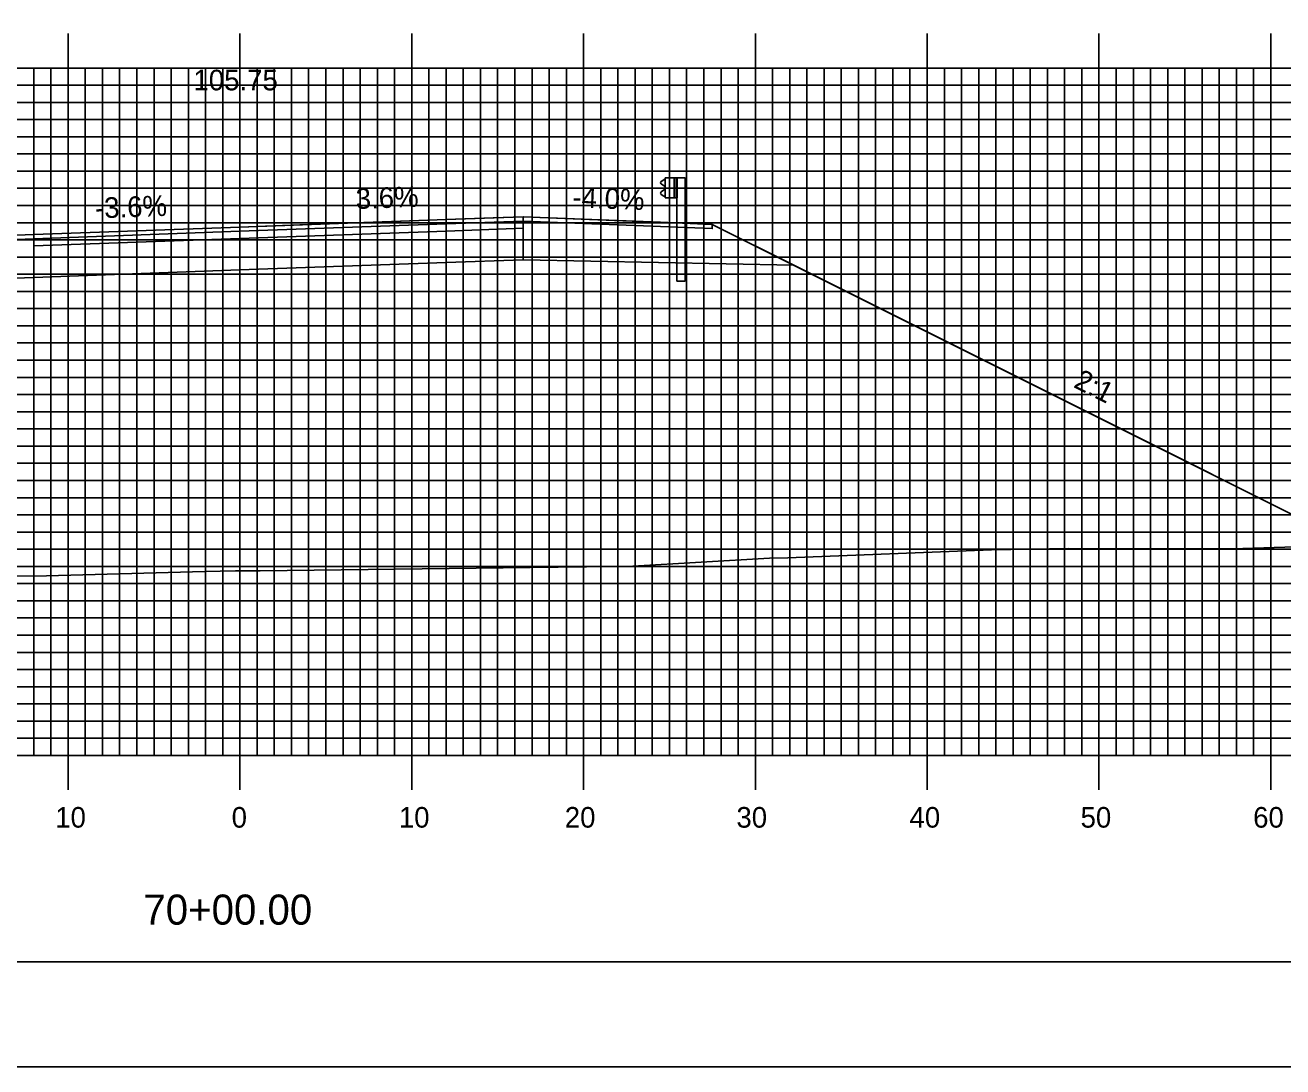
# Model space of a CAD drawing. Extents: x 1760217 to 1760560, y 442591 to 442811.
# Drawn here: x 1760370.2 to 1760443.4, y 442590.5 to 442651.2 of the extents above; entities that cross this region are included whole.
import ezdxf

# ---------------------------------------------------------------- set-up
doc = ezdxf.new("R2010")
doc.units = 0
for name, color, linetype in [('ANNOTATION', 7, 'Continuous'), ('BORDER', 7, 'Continuous'), ('D_Guardrail_Beam_Rt', 7, 'Continuous'), ('D_Roadway_Centerline', 7, 'Continuous'), ('D_Roadway_Centerline_Text', 7, 'Continuous'), ('D_Roadway_Edge_Shoulder', 7, 'Continuous'), ('D_Roadway_Edge_TW', 7, 'Continuous'), ('D_Roadway_Pavement', 7, 'Continuous'), ('D_Roadway_SlopeLines', 7, 'Continuous'), ('D_Roadway_SubGrade', 7, 'Continuous'), ('H_V ANNOTATION', 7, 'Continuous'), ('MAJOR', 7, 'Continuous'), ('MINOR', 7, 'Continuous'), ('PLOT BOUNDARY', 7, 'Continuous'), ('S_Roadway_Centerline', 7, 'Continuous')]:
    doc.layers.add(name, color=color, linetype=linetype)

msp = doc.modelspace()

# ---------------------------------------------------------------- linework, layer by layer
at = {"layer": 'BORDER'}
msp.add_lwpolyline([(1760233.101, 442596.665), (1760553.101, 442596.665), (1760553.101, 442806.665), (1760233.101, 442806.665)], close=True, dxfattribs=at)
at = {"layer": 'D_Guardrail_Beam_Rt'}
for p, q in [((1760407.369, 442642.167), (1760407.226, 442642.067)), ((1760407.459, 442642.188), (1760407.385, 442642.174)), ((1760407.459, 442642.272), (1760408.147, 442642.272)), ((1760407.459, 442641.105), (1760407.459, 442642.272)), ((1760407.98, 442642.272), (1760407.98, 442641.105)), ((1760408.084, 442642.272), (1760408.084, 442641.105)), ((1760408.147, 442642.272), (1760408.617, 442642.272)), ((1760408.147, 442642.272), (1760408.147, 442641.105)), ((1760408.617, 442642.272), (1760408.617, 442636.272)), ((1760407.226, 442641.924), (1760407.421, 442641.788)), ((1760407.421, 442641.589), (1760407.226, 442641.453)), ((1760407.226, 442641.309), (1760407.369, 442641.209)), ((1760407.455, 442641.723), (1760407.455, 442641.653)), ((1760407.385, 442641.203), (1760407.459, 442641.188)), ((1760408.147, 442641.105), (1760407.459, 442641.105)), ((1760408.126, 442636.272), (1760408.126, 442641.105)), ((1760408.126, 442636.272), (1760408.617, 442636.272))]:
    msp.add_line(p, q, dxfattribs=at)
for centre, major_axis, start_param, end_param in [((1760407.276, 442641.995), (-0.0877, 0), 5.323254, 7.243116), ((1760407.393, 442642.133), (-0.0417, 0), 4.907132, 5.323254), ((1760407.276, 442641.381), (-0.0877, 0), 5.323254, 7.243116), ((1760407.376, 442641.723), (0.0789, 0), 0, 0.959931), ((1760407.376, 442641.653), (0.0789, 0), 5.323254, 6.283185), ((1760407.393, 442641.243), (-0.0417, 0), 0.959931, 1.376053)]:
    msp.add_ellipse(centre, major_axis=major_axis, ratio=0.995501, start_param=start_param, end_param=end_param, dxfattribs=at)
at = {"layer": 'D_Roadway_Centerline'}
msp.add_lwpolyline([(1760368.655, 442638.9), (1760370.7, 442638.982), (1760382.699, 442639.414), (1760382.701, 442639.414), (1760382.703, 442639.414), (1760385.673, 442639.521), (1760394.701, 442639.846), (1760397.434, 442639.945), (1760399.188, 442640.008), (1760399.191, 442640.008), (1760404.983, 442639.776), (1760407.188, 442639.688), (1760410.189, 442639.568), (1760414.939, 442637.193), (1760431.037, 442629.144), (1760447.516, 442620.904)], dxfattribs=at)
at = {"layer": 'D_Roadway_Edge_Shoulder'}
for points in [[(1760399.188, 442640.008), (1760407.188, 442639.688), (1760407.188, 442639.688), (1760410.189, 442639.568), (1760410.189, 442639.318), (1760399.188, 442639.758)], [(1760370.7, 442638.982), (1760362.701, 442638.662), (1760362.701, 442638.662), (1760359.701, 442638.542), (1760359.701, 442638.292), (1760370.7, 442638.732)]]:
    msp.add_lwpolyline(points, close=True, dxfattribs=at)
at = {"layer": 'D_Roadway_Edge_TW'}
for points in [[(1760370.7, 442638.732), (1760370.7, 442638.982), (1760382.701, 442639.414), (1760394.701, 442639.846), (1760394.701, 442639.596), (1760382.701, 442639.164)], [(1760394.701, 442639.846), (1760399.188, 442640.008), (1760399.188, 442639.758), (1760394.701, 442639.596)]]:
    msp.add_lwpolyline(points, close=True, dxfattribs=at)
at = {"layer": 'D_Roadway_Pavement'}
for points in [[(1760370.7, 442638.315), (1760370.7, 442638.732), (1760382.701, 442639.164), (1760394.701, 442639.596), (1760394.701, 442639.179), (1760382.701, 442638.747)], [(1760394.701, 442639.596), (1760399.188, 442639.758), (1760399.188, 442639.341), (1760394.701, 442639.179)]]:
    msp.add_lwpolyline(points, close=True, dxfattribs=at)
for points in [[(1760399.188, 442639.758), (1760399.188, 442639.341)], [(1760399.188, 442639.758), (1760399.188, 442639.341)], [(1760370.7, 442638.732), (1760370.7, 442638.315)]]:
    msp.add_lwpolyline(points, dxfattribs=at)
at = {"layer": 'D_Roadway_SlopeLines'}
msp.add_lwpolyline([(1760410.189, 442639.568), (1760447.516, 442620.904)], dxfattribs=at)
at = {"layer": 'D_Roadway_SubGrade'}
for points in [[(1760370.7, 442636.482), (1760370.7, 442638.315), (1760382.701, 442638.747), (1760394.701, 442639.179), (1760394.701, 442637.346), (1760382.701, 442636.914)], [(1760394.701, 442639.179), (1760399.188, 442639.341), (1760399.188, 442637.508), (1760394.701, 442637.346)], [(1760399.188, 442639.341), (1760399.188, 442639.758), (1760410.189, 442639.318), (1760410.189, 442639.568), (1760414.939, 442637.193), (1760399.188, 442637.508)], [(1760370.7, 442638.315), (1760370.7, 442638.732), (1760359.701, 442638.292), (1760359.701, 442638.542), (1760354.408, 442635.895), (1760370.7, 442636.482)]]:
    msp.add_lwpolyline(points, close=True, dxfattribs=at)
at = {"layer": 'MAJOR'}
for p, q in [((1760372.701, 442650.669), (1760372.701, 442648.665)), ((1760382.701, 442650.669), (1760382.701, 442648.665)), ((1760392.701, 442650.669), (1760392.701, 442648.665)), ((1760402.701, 442650.669), (1760402.701, 442648.665)), ((1760412.701, 442650.669), (1760412.701, 442648.665)), ((1760422.701, 442650.669), (1760422.701, 442648.665)), ((1760432.701, 442650.669), (1760432.701, 442648.665)), ((1760442.701, 442650.669), (1760442.701, 442648.665)), ((1760242.701, 442648.665), (1760522.701, 442648.665)), ((1760242.701, 442648.665), (1760522.701, 442648.665)), ((1760372.701, 442608.665), (1760372.701, 442648.665)), ((1760382.701, 442608.665), (1760382.701, 442648.665)), ((1760392.701, 442608.665), (1760392.701, 442648.665)), ((1760402.701, 442608.665), (1760402.701, 442648.665)), ((1760412.701, 442608.665), (1760412.701, 442648.665)), ((1760422.701, 442608.665), (1760422.701, 442648.665)), ((1760432.701, 442608.665), (1760432.701, 442648.665)), ((1760442.701, 442608.665), (1760442.701, 442648.665)), ((1760242.701, 442643.665), (1760522.701, 442643.665)), ((1760242.701, 442638.665), (1760522.701, 442638.665)), ((1760242.701, 442633.665), (1760522.701, 442633.665)), ((1760242.701, 442628.665), (1760522.701, 442628.665)), ((1760242.701, 442623.665), (1760522.701, 442623.665)), ((1760242.701, 442618.665), (1760522.701, 442618.665)), ((1760242.701, 442613.665), (1760522.701, 442613.665)), ((1760242.701, 442608.665), (1760522.701, 442608.665)), ((1760242.701, 442608.665), (1760522.701, 442608.665)), ((1760372.701, 442606.661), (1760372.701, 442608.665)), ((1760382.701, 442606.661), (1760382.701, 442608.665)), ((1760392.701, 442606.661), (1760392.701, 442608.665)), ((1760402.701, 442606.661), (1760402.701, 442608.665)), ((1760412.701, 442606.661), (1760412.701, 442608.665)), ((1760422.701, 442606.661), (1760422.701, 442608.665)), ((1760432.701, 442606.661), (1760432.701, 442608.665)), ((1760442.701, 442606.661), (1760442.701, 442608.665))]:
    msp.add_line(p, q, dxfattribs=at)
at = {"layer": 'MINOR'}
for p, q in [((1760370.701, 442608.665), (1760370.701, 442648.665)), ((1760371.701, 442608.665), (1760371.701, 442648.665)), ((1760373.701, 442608.665), (1760373.701, 442648.665)), ((1760374.701, 442608.665), (1760374.701, 442648.665)), ((1760375.701, 442608.665), (1760375.701, 442648.665)), ((1760376.701, 442608.665), (1760376.701, 442648.665)), ((1760377.701, 442608.665), (1760377.701, 442648.665)), ((1760378.701, 442608.665), (1760378.701, 442648.665)), ((1760379.701, 442608.665), (1760379.701, 442648.665)), ((1760380.701, 442608.665), (1760380.701, 442648.665)), ((1760381.701, 442608.665), (1760381.701, 442648.665)), ((1760383.701, 442608.665), (1760383.701, 442648.665)), ((1760384.701, 442608.665), (1760384.701, 442648.665)), ((1760385.701, 442608.665), (1760385.701, 442648.665)), ((1760386.701, 442608.665), (1760386.701, 442648.665)), ((1760387.701, 442608.665), (1760387.701, 442648.665)), ((1760388.701, 442608.665), (1760388.701, 442648.665)), ((1760389.701, 442608.665), (1760389.701, 442648.665)), ((1760390.701, 442608.665), (1760390.701, 442648.665)), ((1760391.701, 442608.665), (1760391.701, 442648.665)), ((1760393.701, 442608.665), (1760393.701, 442648.665)), ((1760394.701, 442608.665), (1760394.701, 442648.665)), ((1760395.701, 442608.665), (1760395.701, 442648.665)), ((1760396.701, 442608.665), (1760396.701, 442648.665)), ((1760397.701, 442608.665), (1760397.701, 442648.665)), ((1760398.701, 442608.665), (1760398.701, 442648.665)), ((1760399.701, 442608.665), (1760399.701, 442648.665)), ((1760400.701, 442608.665), (1760400.701, 442648.665)), ((1760401.701, 442608.665), (1760401.701, 442648.665)), ((1760403.701, 442608.665), (1760403.701, 442648.665)), ((1760404.701, 442608.665), (1760404.701, 442648.665)), ((1760405.701, 442608.665), (1760405.701, 442648.665)), ((1760406.701, 442608.665), (1760406.701, 442648.665)), ((1760407.701, 442608.665), (1760407.701, 442648.665)), ((1760408.701, 442608.665), (1760408.701, 442648.665)), ((1760409.701, 442608.665), (1760409.701, 442648.665)), ((1760410.701, 442608.665), (1760410.701, 442648.665)), ((1760411.701, 442608.665), (1760411.701, 442648.665)), ((1760413.701, 442608.665), (1760413.701, 442648.665)), ((1760414.701, 442608.665), (1760414.701, 442648.665)), ((1760415.701, 442608.665), (1760415.701, 442648.665)), ((1760416.701, 442608.665), (1760416.701, 442648.665)), ((1760417.701, 442608.665), (1760417.701, 442648.665)), ((1760418.701, 442608.665), (1760418.701, 442648.665)), ((1760419.701, 442608.665), (1760419.701, 442648.665)), ((1760420.701, 442608.665), (1760420.701, 442648.665)), ((1760421.701, 442608.665), (1760421.701, 442648.665)), ((1760423.701, 442608.665), (1760423.701, 442648.665)), ((1760424.701, 442608.665), (1760424.701, 442648.665)), ((1760425.701, 442608.665), (1760425.701, 442648.665)), ((1760426.701, 442608.665), (1760426.701, 442648.665)), ((1760427.701, 442608.665), (1760427.701, 442648.665)), ((1760428.701, 442608.665), (1760428.701, 442648.665)), ((1760429.701, 442608.665), (1760429.701, 442648.665)), ((1760430.701, 442608.665), (1760430.701, 442648.665)), ((1760431.701, 442608.665), (1760431.701, 442648.665)), ((1760433.701, 442608.665), (1760433.701, 442648.665)), ((1760434.701, 442608.665), (1760434.701, 442648.665)), ((1760435.701, 442608.665), (1760435.701, 442648.665)), ((1760436.701, 442608.665), (1760436.701, 442648.665)), ((1760437.701, 442608.665), (1760437.701, 442648.665)), ((1760438.701, 442608.665), (1760438.701, 442648.665)), ((1760439.701, 442608.665), (1760439.701, 442648.665)), ((1760440.701, 442608.665), (1760440.701, 442648.665)), ((1760441.701, 442608.665), (1760441.701, 442648.665)), ((1760242.701, 442647.665), (1760522.701, 442647.665)), ((1760242.701, 442646.665), (1760522.701, 442646.665)), ((1760242.701, 442645.665), (1760522.701, 442645.665)), ((1760242.701, 442644.665), (1760522.701, 442644.665)), ((1760242.701, 442642.665), (1760522.701, 442642.665)), ((1760242.701, 442641.665), (1760522.701, 442641.665)), ((1760242.701, 442640.665), (1760522.701, 442640.665)), ((1760242.701, 442639.665), (1760522.701, 442639.665)), ((1760242.701, 442637.665), (1760522.701, 442637.665)), ((1760242.701, 442636.665), (1760522.701, 442636.665)), ((1760242.701, 442635.665), (1760522.701, 442635.665)), ((1760242.701, 442634.665), (1760522.701, 442634.665)), ((1760242.701, 442632.665), (1760522.701, 442632.665)), ((1760242.701, 442631.665), (1760522.701, 442631.665)), ((1760242.701, 442630.665), (1760522.701, 442630.665)), ((1760242.701, 442629.665), (1760522.701, 442629.665)), ((1760242.701, 442627.665), (1760522.701, 442627.665)), ((1760242.701, 442626.665), (1760522.701, 442626.665)), ((1760242.701, 442625.665), (1760522.701, 442625.665)), ((1760242.701, 442624.665), (1760522.701, 442624.665)), ((1760242.701, 442622.665), (1760522.701, 442622.665)), ((1760242.701, 442621.665), (1760522.701, 442621.665)), ((1760242.701, 442620.665), (1760522.701, 442620.665)), ((1760242.701, 442619.665), (1760522.701, 442619.665)), ((1760242.701, 442617.665), (1760522.701, 442617.665)), ((1760242.701, 442616.665), (1760522.701, 442616.665)), ((1760242.701, 442615.665), (1760522.701, 442615.665)), ((1760242.701, 442614.665), (1760522.701, 442614.665)), ((1760242.701, 442612.665), (1760522.701, 442612.665)), ((1760242.701, 442611.665), (1760522.701, 442611.665)), ((1760242.701, 442610.665), (1760522.701, 442610.665)), ((1760242.701, 442609.665), (1760522.701, 442609.665))]:
    msp.add_line(p, q, dxfattribs=at)
at = {"layer": 'PLOT BOUNDARY'}
msp.add_lwpolyline([(1760216.914, 442590.547), (1760556.914, 442590.547), (1760556.914, 442810.547), (1760216.914, 442810.547)], close=True, dxfattribs=at)
at = {"layer": 'S_Roadway_Centerline'}
msp.add_lwpolyline([(1760312.284, 442618.009), (1760318.928, 442618.305), (1760329.666, 442618.553), (1760335.384, 442618.666), (1760340.697, 442618.727), (1760347.315, 442618.852), (1760355.228, 442619.073), (1760359.02, 442619.169), (1760362.034, 442619.126), (1760370.722, 442619.097), (1760380.666, 442619.37), (1760382.441, 442619.415), (1760383.885, 442619.399), (1760399.593, 442619.605), (1760404.504, 442619.654), (1760404.982, 442619.667), (1760405.573, 442619.687), (1760413.525, 442620.141), (1760414.6, 442620.171), (1760426.436, 442620.622), (1760430.946, 442620.704), (1760440.452, 442620.696), (1760447.807, 442620.913)], dxfattribs=at)

# ---------------------------------------------------------------- texts
at = {"layer": 'ANNOTATION'}
for s, rotation, p in [('-3.6%', 2.06165, (1760374.286, 442639.913)), ('3.6%', 2.0631, (1760389.46, 442640.459)), ('-4.0%', 357.70977, (1760402.036, 442640.562)), ('2:1', 333.43411, (1760431.162, 442630.118))]:
    msp.add_text(s, height=1.2, rotation=rotation, dxfattribs=at).set_placement(p)
at = {"layer": 'D_Roadway_Centerline'}
for s, p in [('C', (1760382.696, 442639.414)), ('L', (1760382.701, 442639.407))]:
    msp.add_text(s, height=0.0146, dxfattribs=at).set_placement(p)
at = {"layer": 'D_Roadway_Centerline_Text'}
msp.add_text('105.75', height=1.2, dxfattribs=at).set_placement((1760379.998, 442647.365))
at = {"layer": 'H_V ANNOTATION'}
for s, height, p in [('10', 1.2, (1760371.951, 442604.465)), ('0', 1.2, (1760382.219, 442604.465)), ('10', 1.2, (1760391.951, 442604.465)), ('20', 1.2, (1760401.609, 442604.465)), ('30', 1.2, (1760411.598, 442604.465)), ('40', 1.2, (1760421.673, 442604.465)), ('50', 1.2, (1760431.63, 442604.465)), ('60', 1.2, (1760441.673, 442604.465)), ('70+00.00', 1.75, (1760377.082, 442598.821))]:
    msp.add_text(s, height=height, dxfattribs=at).set_placement(p)

doc.saveas('drawing.dxf')
